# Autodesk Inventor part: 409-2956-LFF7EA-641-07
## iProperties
Shininess: 64.0
Angle Display Precision: 2
Document Length Units: 11272
Document Angle Units: 11279
Document Time Units: 11290
Document Mass Units: 11286
Document Length Units Precision: 3
Document Angle Units Precision: 2
Compacted: True
Created: 2002-04
Part Number: 409-2956-LFF7EA-641-07
Description: PSL MOUNT ANGLE
Document SubType Name: Modeling
Designer: S. Boerckel
Mass: 457.732 g
Surface Area: 261.703 cm^2
Volume: 58.2356 cm^3
Density: 7.86 g/cm^3
Cost Center: 2 x 2 x 3/16 HR ANGLE
User Status: SAW/PUNCH
Material: ASTM A36 STEEL
Engineer: S. Boerckel
Density: 0.0
Volumn: 0.0
Area: 0.0
PropertySet Name: Model Information
Control State: 0
Master: False
Checked Out: False
SMR: =<COST CENTER> <MATERIAL>
LGTH: 5.000 in
Author: S. Boerckel
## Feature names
1. Extrusion1
2. Hole1
